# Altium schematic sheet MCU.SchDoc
size A4; PageSetup: Record=PageOptions|CenterHorizontal=True|CenterVertical=True|PrintScale=0.98|XCorrection=1.00|YCorrection=1.00|PrintKind=0|BorderSize=5000000|LeftOffset=0|BottomOffset=0|Orientation=2|PaperLength=1000|PaperWidth=1000|Scale=100|PaperSource=7|PrintQuality=-4|MediaType=1|DitherType=10|PaperKind=A4 210x297 ºÁÃ×|PrintScaleMode=1
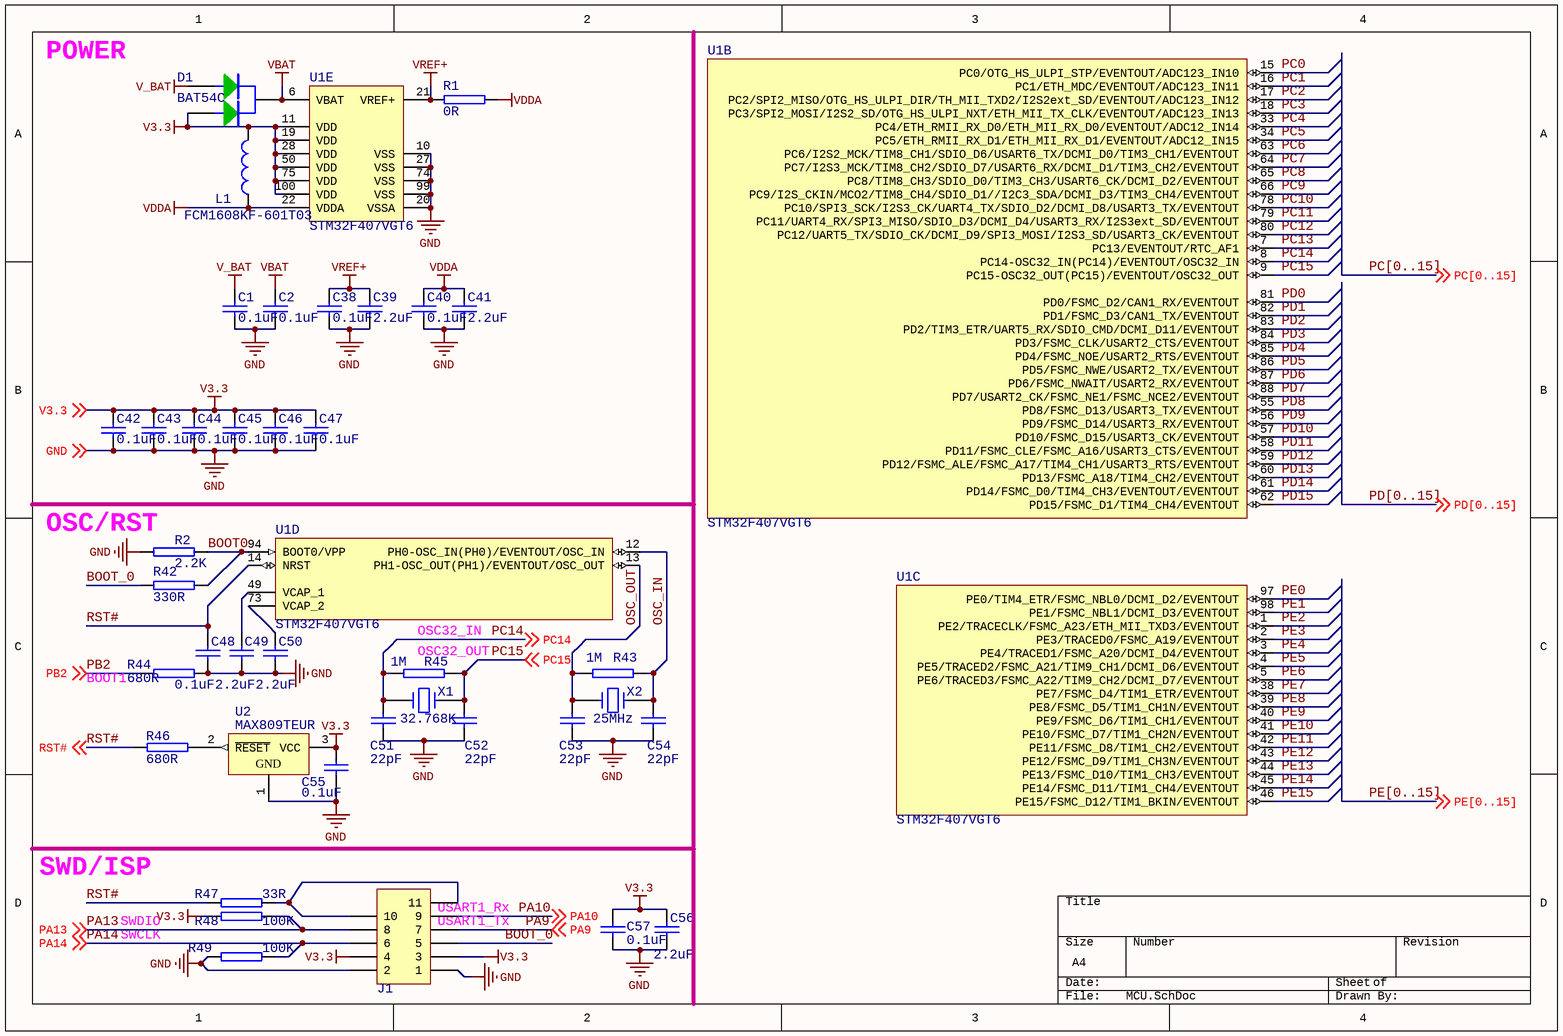
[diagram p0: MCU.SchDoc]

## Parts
C1  0.1uF  [C1608(0603)]
C2  0.1uF  [C1608(0603)]
C38  0.1uF  [C1608(0603)]
C39  2.2uF  [C1608(0603)]
C40  0.1uF  [C1608(0603)]
C41  2.2uF  [C1608(0603)]
C42  0.1uF  [C1608(0603)]
C43  0.1uF  [C1608(0603)]
C44  0.1uF  [C1608(0603)]
C45  0.1uF  [C1608(0603)]
C46  0.1uF  [C1608(0603)]
C47  0.1uF  [C1608(0603)]
C48  0.1uF  [C1608(0603)]
C49  2.2uF  [C1608(0603)]
C50  2.2uF  [C1608(0603)]
C51  22pF  [C1608(0603)]
C52  22pF  [C1608(0603)]
C53  22pF  [C1608(0603)]
C54  22pF  [C1608(0603)]
C55  0.1uF  [C1608(0603)]
C56  2.2uF  [C1608(0603)]
C57  0.1uF  [C1608(0603)]
D1  BAT54C  [SOT23-3_N]
J1  H2.54 6X2  [HDR2X6H]  (value not drawn)
L1  FCM1608KF-601T03  [R1608(0603)]
R1  0R  [R1608(0603)]
R2  2.2K  [R1608(0603)]
R42  330R  [R1608(0603)]
R43  1M  [R1608(0603)]
R44  680R  [R1608(0603)]
R45  1M  [R1608(0603)]
R46  680R  [R1608(0603)]
R47  33R  [R1608(0603)]
R48  100K  [R1608(0603)]
R49  100K  [R1608(0603)]
U1  STM32F407VGT6  [TQFP100_N]  (parts B,C,D,E of 5)
U2  MAX809TEUR  [SOT23-3_N]
X1  32.768K  [FC-135]
X2  25MHz  [XTAL-3225]

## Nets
GND: C1.2 C2.2 C38.2 C39.2 C40.2 C41.2 C42.2 C43.2 C44.2 C45.2 C46.2 C47.2 C48.2 C49.2 C50.2 C51.1 C52.1 C53.1 C54.1 C55.2 C56.2 C57.1 J1.1 J1.2 R2.2 R44.1 R49.1 U1.10(VSS) U1.20(VSSA) U1.27(VSS) U1.74(VSS) U1.99(VSS) U2.1(GND) ; off-sheet GND
V3.3: C42.1 C43.1 C44.1 C45.1 C46.1 C47.1 C55.1 C56.1 C57.2 D1.1 J1.3 J1.4 L1.2 R48.1 U1.11(VDD) U1.19(VDD) U1.28(VDD) U1.50(VDD) U1.75(VDD) U1.100(VDD) U2.3(VCC) ; off-sheet V3.3
V_BAT: C1.1 D1.2
VBAT: C2.1 D1.3 U1.6(VBAT)
VDDA: C40.1 C41.1 L1.1 R1.1 U1.22(VDDA)
VREF+: C38.1 C39.1 R1.2 U1.21(VREF+)
BOOT0: R2.1 R42.2 U1.94(BOOT0/VPP)
BOOT_0: J1.5 R42.1
OSC_IN: C54.2 R43.1 U1.12(PH0-OSC_IN(PH0)/EVENTOUT/OSC_IN) X2.1
OSC_OUT: C53.2 R43.2 U1.13(PH1-OSC_OUT(PH1)/EVENTOUT/OSC_OUT) X2.3
PA9: J1.7 ; off-sheet PA9
PA10: J1.9 ; off-sheet PA10
PA13: J1.8 R48.2 ; off-sheet PA13
PA14: J1.6 R49.2 ; off-sheet PA14
PB2: R44.2 ; off-sheet PB2
PC0: U1.15(PC0/OTG_HS_ULPI_STP/EVENTOUT/ADC123_IN10)
PC1: U1.16(PC1/ETH_MDC/EVENTOUT/ADC123_IN11)
PC2: U1.17(PC2/SPI2_MISO/OTG_HS_ULPI_DIR/TH_MII_TXD2/I2S2ext_SD/EVENTOUT/ADC123_IN12)
PC3: U1.18(PC3/SPI2_MOSI/I2S2_SD/OTG_HS_ULPI_NXT/ETH_MII_TX_CLK/EVENTOUT/ADC123_IN13)
PC4: U1.33(PC4/ETH_RMII_RX_D0/ETH_MII_RX_D0/EVENTOUT/ADC12_IN14)
PC5: U1.34(PC5/ETH_RMII_RX_D1/ETH_MII_RX_D1/EVENTOUT/ADC12_IN15)
PC6: U1.63(PC6/I2S2_MCK/TIM8_CH1/SDIO_D6/USART6_TX/DCMI_D0/TIM3_CH1/EVENTOUT)
PC7: U1.64(PC7/I2S3_MCK/TIM8_CH2/SDIO_D7/USART6_RX/DCMI_D1/TIM3_CH2/EVENTOUT)
PC8: U1.65(PC8/TIM8_CH3/SDIO_D0/TIM3_CH3/USART6_CK/DCMI_D2/EVENTOUT)
PC9: U1.66(PC9/I2S_CKIN/MCO2/TIM8_CH4/SDIO_D1//I2C3_SDA/DCMI_D3/TIM3_CH4/EVENTOUT)
PC10: U1.78(PC10/SPI3_SCK/I2S3_CK/UART4_TX/SDIO_D2/DCMI_D8/USART3_TX/EVENTOUT)
PC11: U1.79(PC11/UART4_RX/SPI3_MISO/SDIO_D3/DCMI_D4/USART3_RX/I2S3ext_SD/EVENTOUT)
PC12: U1.80(PC12/UART5_TX/SDIO_CK/DCMI_D9/SPI3_MOSI/I2S3_SD/USART3_CK/EVENTOUT)
PC13: U1.7(PC13/EVENTOUT/RTC_AF1)
PC14: C51.2 R45.2 U1.8(PC14-OSC32_IN(PC14)/EVENTOUT/OSC32_IN) X1.2 ; off-sheet PC14
PC15: C52.2 R45.1 U1.9(PC15-OSC32_OUT(PC15)/EVENTOUT/OSC32_OUT) X1.1 ; off-sheet PC15
PD0: U1.81(PD0/FSMC_D2/CAN1_RX/EVENTOUT)
PD1: U1.82(PD1/FSMC_D3/CAN1_TX/EVENTOUT)
PD2: U1.83(PD2/TIM3_ETR/UART5_RX/SDIO_CMD/DCMI_D11/EVENTOUT)
PD3: U1.84(PD3/FSMC_CLK/USART2_CTS/EVENTOUT)
PD4: U1.85(PD4/FSMC_NOE/USART2_RTS/EVENTOUT)
PD5: U1.86(PD5/FSMC_NWE/USART2_TX/EVENTOUT)
PD6: U1.87(PD6/FSMC_NWAIT/USART2_RX/EVENTOUT)
PD7: U1.88(PD7/USART2_CK/FSMC_NE1/FSMC_NCE2/EVENTOUT)
PD8: U1.55(PD8/FSMC_D13/USART3_TX/EVENTOUT)
PD9: U1.56(PD9/FSMC_D14/USART3_RX/EVENTOUT)
PD10: U1.57(PD10/FSMC_D15/USART3_CK/EVENTOUT)
PD11: U1.58(PD11/FSMC_CLE/FSMC_A16/USART3_CTS/EVENTOUT)
PD12: U1.59(PD12/FSMC_ALE/FSMC_A17/TIM4_CH1/USART3_RTS/EVENTOUT)
PD13: U1.60(PD13/FSMC_A18/TIM4_CH2/EVENTOUT)
PD14: U1.61(PD14/FSMC_D0/TIM4_CH3/EVENTOUT/EVENTOUT)
PD15: U1.62(PD15/FSMC_D1/TIM4_CH4/EVENTOUT)
PE0: U1.97(PE0/TIM4_ETR/FSMC_NBL0/DCMI_D2/EVENTOUT)
PE1: U1.98(PE1/FSMC_NBL1/DCMI_D3/EVENTOUT)
PE2: U1.1(PE2/TRACECLK/FSMC_A23/ETH_MII_TXD3/EVENTOUT)
PE3: U1.2(PE3/TRACED0/FSMC_A19/EVENTOUT)
PE4: U1.3(PE4/TRACED1/FSMC_A20/DCMI_D4/EVENTOUT)
PE5: U1.4(PE5/TRACED2/FSMC_A21/TIM9_CH1/DCMI_D6/EVENTOUT)
PE6: U1.5(PE6/TRACED3/FSMC_A22/TIM9_CH2/DCMI_D7/EVENTOUT)
PE7: U1.38(PE7/FSMC_D4/TIM1_ETR/EVENTOUT)
PE8: U1.39(PE8/FSMC_D5/TIM1_CH1N/EVENTOUT)
PE9: U1.40(PE9/FSMC_D6/TIM1_CH1/EVENTOUT)
PE10: U1.41(PE10/FSMC_D7/TIM1_CH2N/EVENTOUT)
PE11: U1.42(PE11/FSMC_D8/TIM1_CH2/EVENTOUT)
PE12: U1.43(PE12/FSMC_D9/TIM1_CH3N/EVENTOUT)
PE13: U1.44(PE13/FSMC_D10/TIM1_CH3/EVENTOUT)
PE14: U1.45(PE14/FSMC_D11/TIM1_CH4/EVENTOUT)
PE15: U1.46(PE15/FSMC_D12/TIM1_BKIN/EVENTOUT)
RST#: C48.1 R46.1 R47.2 U1.14(NRST) ; off-sheet RST#
NetC49_1: C49.1 U1.49(VCAP_1)
NetC50_1: C50.1 U1.73(VCAP_2)
NetJ1_10: J1.10 J1.11 R47.1
NetR46_2: R46.2 U2.2(~{RESET})

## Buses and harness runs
bus PC[0..15]
bus PD[0..15]
bus PE[0..15]

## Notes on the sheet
- POWER
- (near R2) OSC/RST
- (near U1) OSC32_IN
- (near R45) OSC32_OUT
- (near R44) BOOT1
- SWD/ISP
- SWDIO
- (near J1) USART1_Tx
- (near J1) USART1_Rx
- SWCLK

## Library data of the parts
C1 C2 C38-C57 = CAP: Capacitor
J1 = Header 6X2: Header, 6-Pin, Dual row
L1 = Inductor: Code_IEC: 1005; Value: 10mH
R1 R2 R42-R49 = R
U1 = STM32F407VGT6: ARM Cortex-M4 32b MCU+FPU, 210DMIP, 1024 kB Flash, 192+4 kB RAM, Camera, 82 I/Os, 100-pin LQFP, -40 to +85°C, Tray; Internal RAM: 192kB; Operating Frequency (Processor Speed): 168MHz; A/D Converter: 16x12-bit; D/A Converter: 2x12-bit; 16-bit Timers (IC/OC/PWM): 12x16-bit(24/24/30); 32-bit Timer (IC/OC/PWM): 2x32-bit (8/8/8); Other Timer Functions: 2xWDG, RTC, 24-bit down counter; Serial Interface: 3xSPI/2xI2S/2xI2C/3xUSART(IrDa, ISO7816)/3xUART/2xUSB OTG FS/HS, 2xCAN/Ethernet MAC10/100, SDIO
U2 = MAX6520EUR-T: 3-Terminal, 1.2V Voltage Reference
X1 X2 = CRYSTAL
